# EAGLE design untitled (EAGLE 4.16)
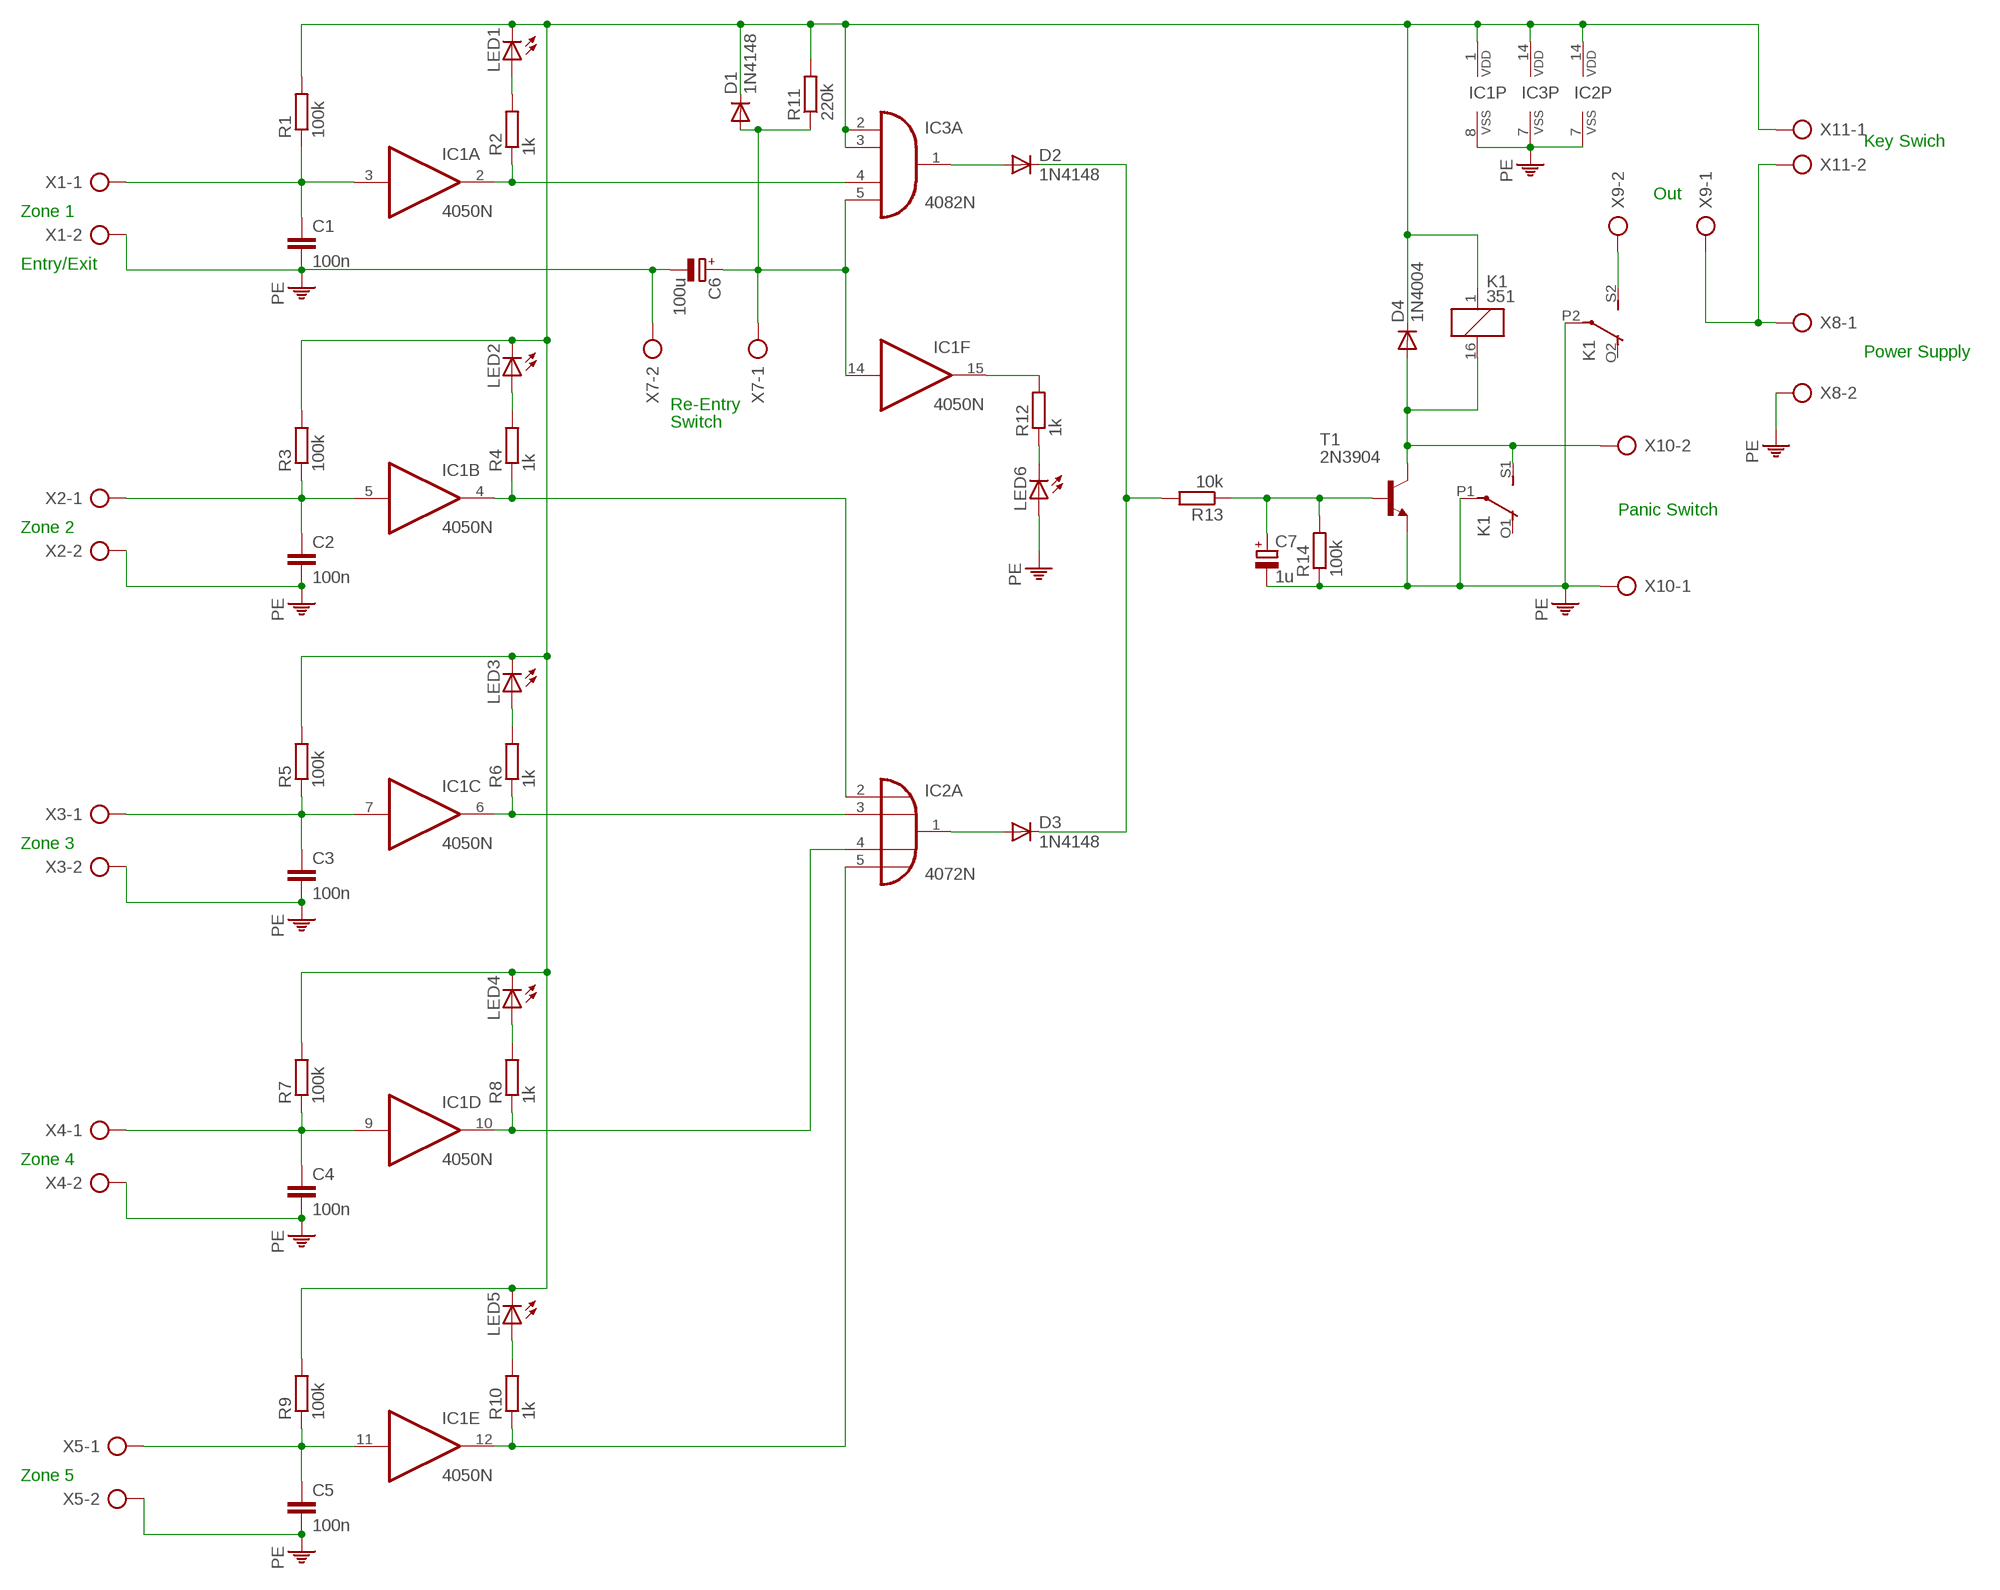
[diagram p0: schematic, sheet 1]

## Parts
C1  100n  C-EU050-024X044  [C050-024X044]
C2  100n  C-EU050-024X044  [C050-024X044]
C3  100n  C-EU050-024X044  [C050-024X044]
C4  100n  C-EU050-024X044  [C050-024X044]
C5  100n  C-EU050-024X044  [C050-024X044]
C6  100u  CPOL-EUE5-8.5  [E5-8,5]
C7  1u  CPOL-EUE5-6  [E5-6]
D1  1N4148  [DO35-10]
D2  1N4148  [DO35-10]
D3  1N4148  [DO35-10]
D4  1N4004  [DO41-10]
IC1  4050N  [DIL16]
IC2  4072N  [DIL14]
IC3  4082N  [DIL14]
K1  351  [351]
LED1  LED5MM  [LED5MM]
LED2  LED5MM  [LED5MM]
LED3  LED5MM  [LED5MM]
LED4  LED5MM  [LED5MM]
LED5  LED5MM  [LED5MM]
LED6  LED5MM  [LED5MM]
R1  100k  R-EU_0207/10  [0207/10]
R2  1k  R-EU_0207/10  [0207/10]
R3  100k  R-EU_0207/10  [0207/10]
R4  1k  R-EU_0207/10  [0207/10]
R5  100k  R-EU_0207/10  [0207/10]
R6  1k  R-EU_0207/10  [0207/10]
R7  100k  R-EU_0207/10  [0207/10]
R8  1k  R-EU_0207/10  [0207/10]
R9  100k  R-EU_0207/10  [0207/10]
R10  1k  R-EU_0207/10  [0207/10]
R11  220k  R-EU_0207/10  [0207/10]
R12  1k  R-EU_0207/10  [0207/10]
R13  10k  R-EU_0207/10  [0207/10]
R14  100k  R-EU_0207/10  [0207/10]
T1  2N3904  [TO92]
X1  AK300/2  [AK300/2]
X2  AK300/2  [AK300/2]
X3  AK300/2  [AK300/2]
X4  AK300/2  [AK300/2]
X5  AK300/2  [AK300/2]
X7  AK300/2  [AK300/2]
X8  AK300/2  [AK300/2]
X9  AK300/2  [AK300/2]
X10  AK300/2  [AK300/2]
X11  AK300/2  [AK300/2]

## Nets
+12V: D1.C D4.C IC1.1(P:VDD) IC2.14(P:VDD) IC3.2(A:I0) IC3.3(A:I1) IC3.14(P:VDD) K1.1 LED1.K(C) LED2.K(C) LED3.K(C) LED4.K(C) LED5.K(C) R1.2 R3.2 R5.2 R7.2 R9.2 R11.2 X11.1
N$1: C1.1 IC1.3(A:I) R1.1 X1.1
N$2: IC1.2(A:O) IC3.4(A:I2) R2.1
N$3: LED1.A R2.2
N$4: C6.+ D1.A IC1.14(F:I) IC3.5(A:I3) R11.1 X7.1
N$5: LED2.A R4.2
N$6: C2.1 IC1.5(B:I) R3.1 X2.1
N$7: LED3.A R6.2
N$8: IC1.4(B:O) IC2.2(A:I0) R4.1
N$9: LED4.A R8.2
N$10: IC1.15(F:O) R12.2
N$11: LED6.K(C) R12.1
N$12: LED5.A R10.2
N$13: IC1.6(C:O) IC2.3(A:I1) R6.1
N$14: C3.1 IC1.7(C:I) R5.1 X3.1
N$15: D3.A IC2.1(A:O)
N$16: D2.A IC3.1(A:O)
N$17: C4.1 IC1.9(D:I) R7.1 X4.1
N$18: IC1.10(D:O) IC2.4(A:I2) R8.1
N$20: D2.C D3.C R13.2
N$21: C5.1 IC1.11(E:I) R9.1 X5.1
N$22: IC1.12(E:O) IC2.5(A:I3) R10.1
N$24: C7.+ R13.1 R14.2 T1.2(B)
N$26: D4.A K1.16 K1.S1(2:S) T1.1(C) X10.2
N$27: K1.S2(3:S) X9.2
N$28: X8.1 X9.1 X11.2
PE: C1.2 C2.2 C3.2 C4.2 C5.2 C6.- C7.- IC1.8(P:VSS) IC2.7(P:VSS) IC3.7(P:VSS) K1.P1(2:P) K1.P2(3:P) LED6.A R14.1 T1.3(E) X1.2 X2.2 X3.2 X4.2 X5.2 X7.2 X8.2 X10.1
Unconnected: IC2.9(B:I0) IC2.10(B:I1) IC2.11(B:I2) IC2.12(B:I3) IC2.13(B:O) IC3.9(B:I0) IC3.10(B:I1) IC3.11(B:I2) IC3.12(B:I3) IC3.13(B:O) K1.O1(2:O) K1.O2(3:O)

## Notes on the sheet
- Key Swich
- Out
- Zone 1
- Entry/Exit
- Power Supply
- Re-Entry
- Switch
- Panic Switch
- Zone 2
- Zone 3
- Zone 4
- Zone 5

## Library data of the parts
C1-C5 = rcl:C-EU: CAPACITOR, European symbol
C6 C7 = rcl:CPOL-EU: POLARIZED CAPACITOR, European symbol
D1-D3 = diode:1N4148: DIODE
D4 = diode:1N4004: DIODE
IC1 = 40xx:4050: Hex non-inverting BUFFER
IC2 = 40xx:4072: Dual 4-input OR
IC3 = 40xx:4082: Dual 4-input AND
K1 = relay:351: RELAY 2 x switch, Omron
LED1-LED6 = led:LED: LED
R1-R14 = rcl:R-EU_: RESISTOR, European symbol
T1 = transistor:2N3904: NPN TRANSISTOR
X1-X5 X7-X11 = con-ptr500:AK300/2: CONNECTOR

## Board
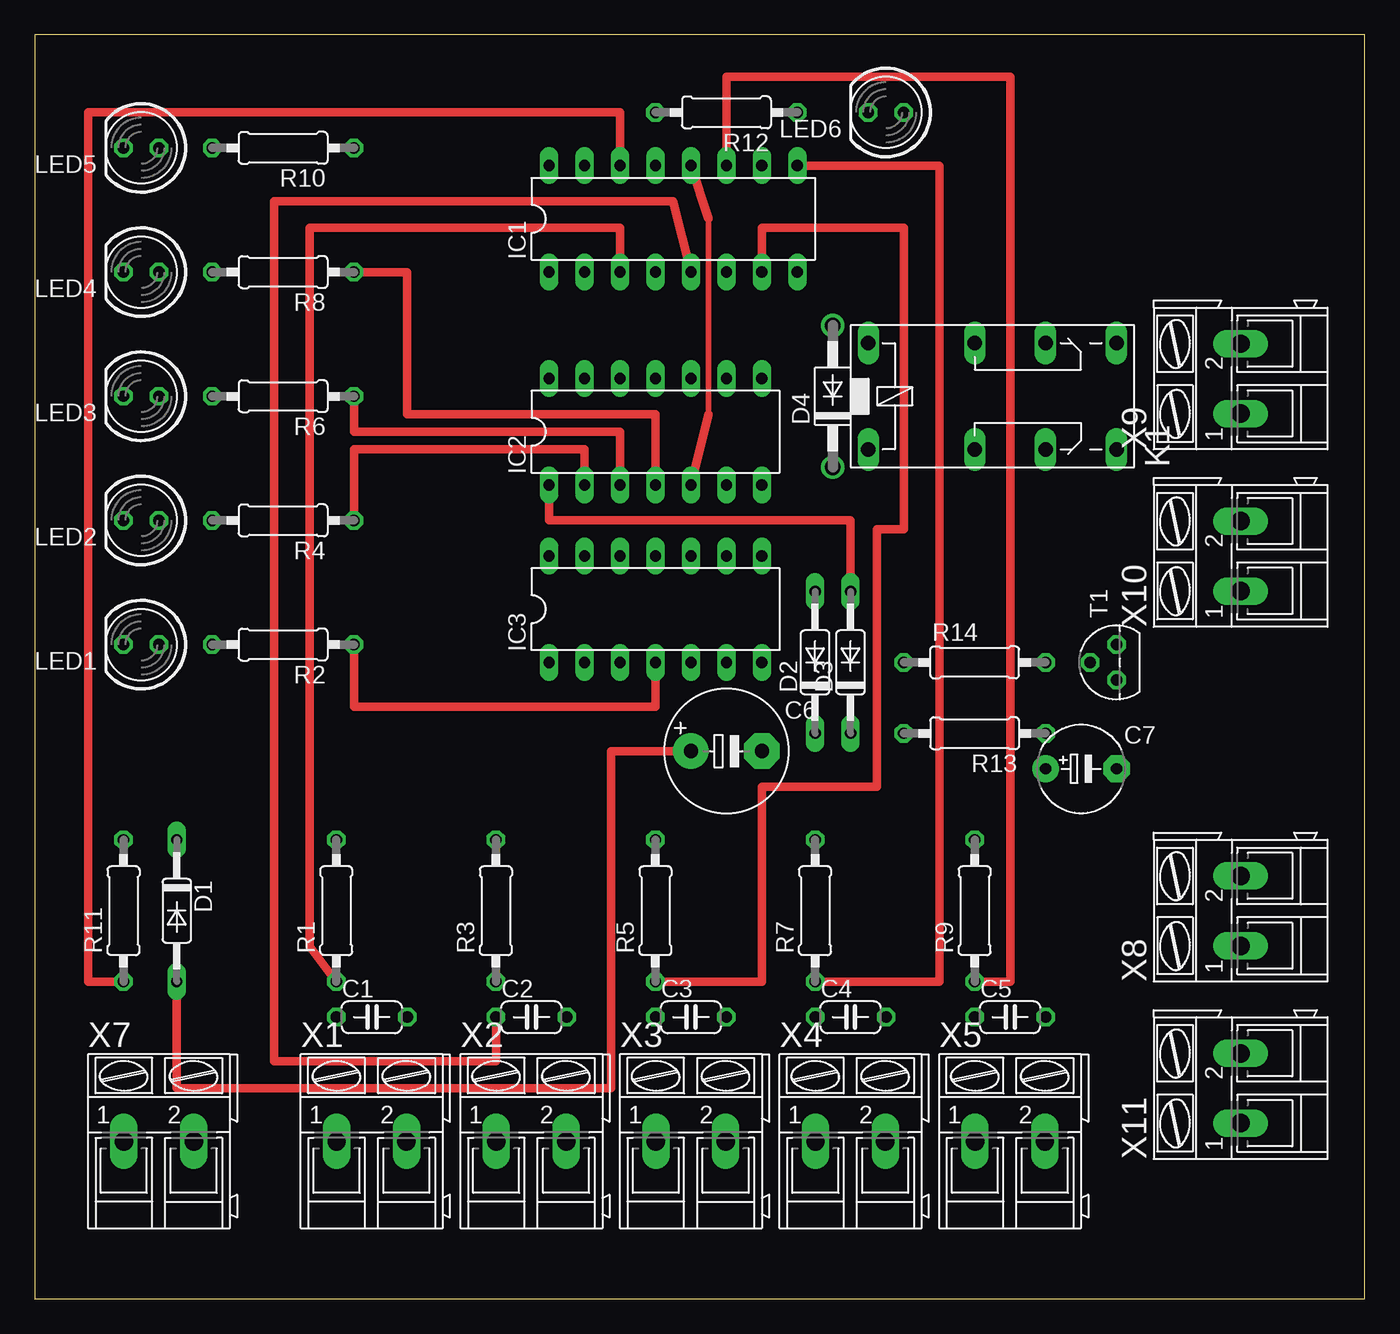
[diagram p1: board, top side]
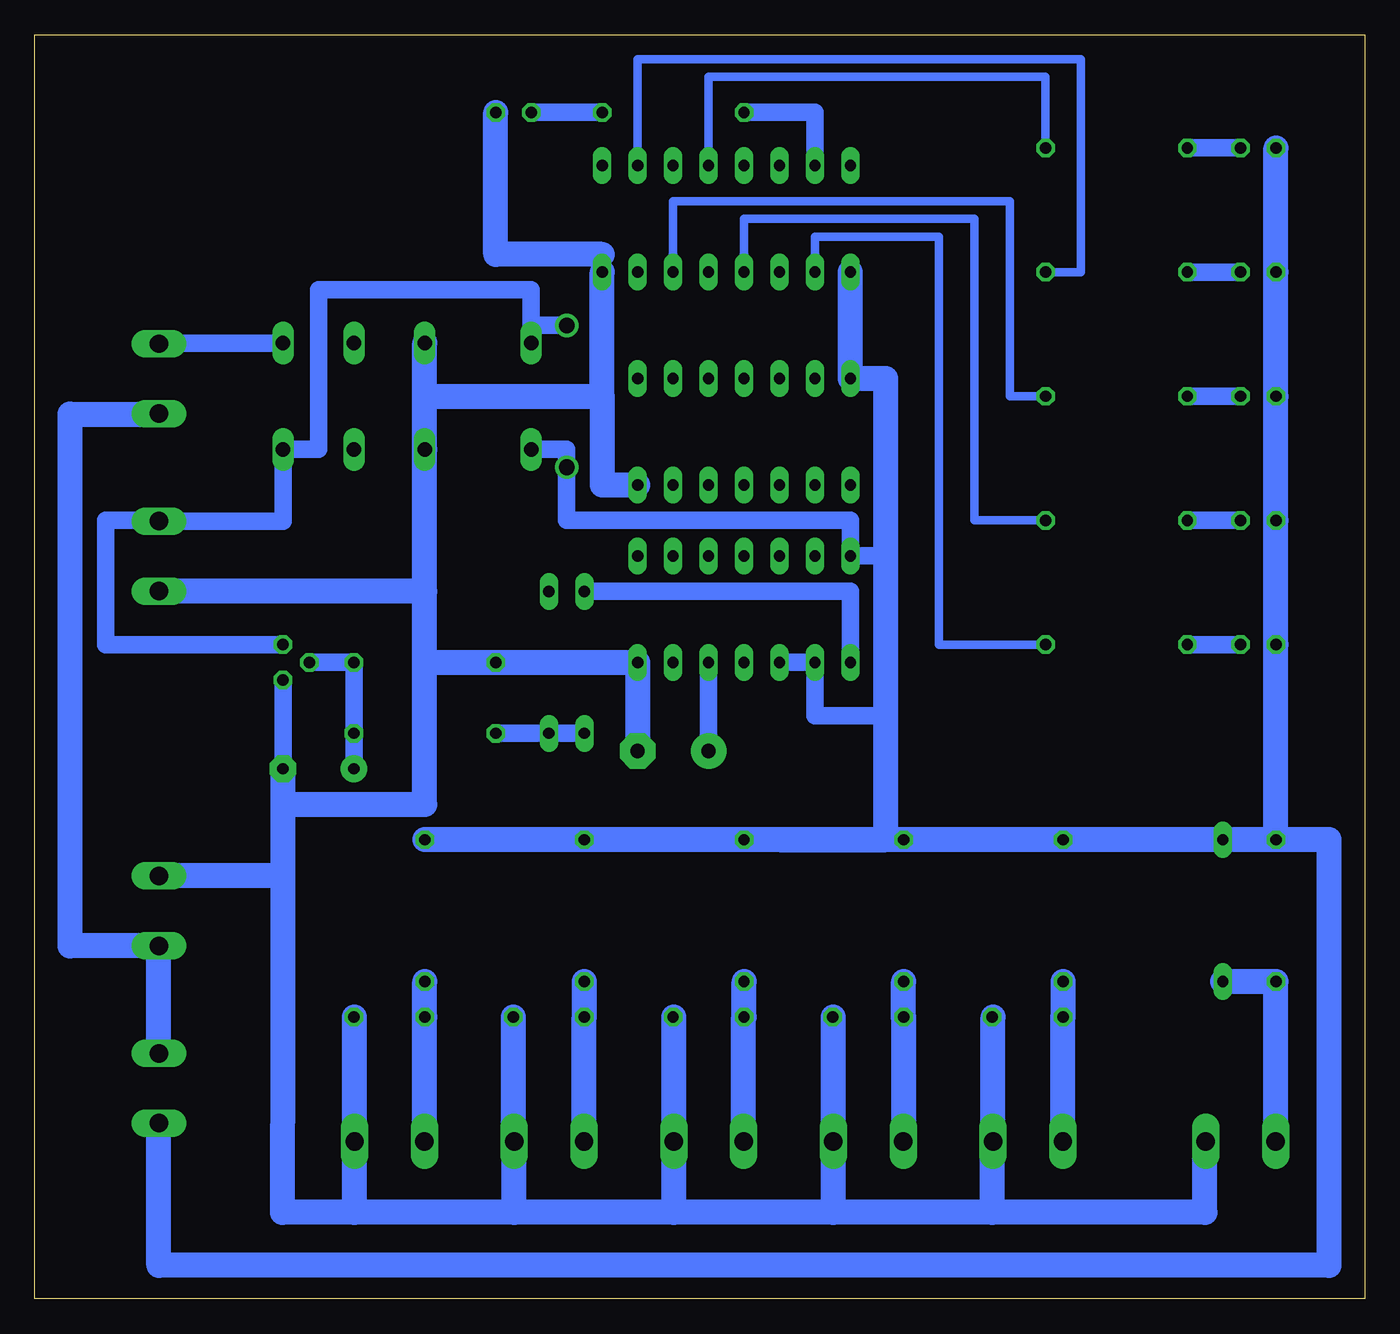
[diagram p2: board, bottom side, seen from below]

Size 95.23 x 90.48 mm. Coordinates in mm from the lower left corner, seen from the top.
Outline: 0,0 95.23,0 95.23,90.48 0,90.48 0,0
Copper layers (1*16): Fls 0.035mm / dielectric 1.5mm / Alsó   0.035mm
Design rules "default": minimum track width 10mil, minimum drill 24mil, track to track 8mil, track to pad 8mil, pad to pad 8mil, via to via 8mil, smd to smd 8mil, copper to edge 40mil, drill to drill 8mil, minimum pad ring 10mil, minimum via ring 8mil, stop-mask expansion 4mil, vias tented up to drill 0mil, thermal gap 10mil

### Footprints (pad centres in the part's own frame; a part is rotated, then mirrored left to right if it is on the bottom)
C050-024X044 = drill 0.813 octagon: 1 -2.54,0; 2 2.54,0
E5-8,5 = drill 1.016 pad 2.54 round: + -2.54,0 | drill 1.016 pad 2.54 octagon: - 2.54,0
E5-6 = drill 0.813 pad 1.905 round: + -2.54,0 | drill 0.813 pad 1.905 octagon: - 2.54,0
DO35-10 = drill 0.813 long: A 5.08,0; C -5.08,0
DO41-10 = drill 1.118 round: A 5.08,0; C -5.08,0
DIL16 = drill 0.813 long: 1 -8.89,-3.81; 2 -6.35,-3.81; 3 -3.81,-3.81; 4 -1.27,-3.81; 5 1.27,-3.81; 6 3.81,-3.81; 7 6.35,-3.81; 8 8.89,-3.81; 9 8.89,3.81; 10 6.35,3.81; 11 3.81,3.81; 12 1.27,3.81; 13 -1.27,3.81; 14 -3.81,3.81; 15 -6.35,3.81; 16 -8.89,3.81
DIL14 = drill 0.813 long: 1 -7.62,-3.81; 2 -5.08,-3.81; 3 -2.54,-3.81; 4 0,-3.81; 5 2.54,-3.81; 6 5.08,-3.81; 7 7.62,-3.81; 8 7.62,3.81; 9 5.08,3.81; 10 2.54,3.81; 11 0,3.81; 12 -2.54,3.81; 13 -5.08,3.81; 14 -7.62,3.81
351 = drill 1.016 long: 1 -3.81,-3.81; 16 -3.81,3.81; O1 8.89,-3.81; O2 8.89,3.81; P1 3.81,-3.81; P2 3.81,3.81; S1 13.97,-3.81; S2 13.97,3.81
LED5MM = drill 0.813 octagon: A -1.27,0; K 1.27,0
0207/10 = drill 0.813 octagon: 1 -5.08,0; 2 5.08,0
TO92 = drill 0.813 octagon: 1 1.27,0; 2 0,1.905; 3 -1.27,0
AK300/2 = drill 1.321 long: 1 -2.515,0; 2 2.489,0

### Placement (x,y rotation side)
C1  24.12,20.16 0 top
C2  35.55,20.16 0 top
C3  46.98,20.16 0 top
C4  58.41,20.16 0 top
C5  69.84,20.16 0 top
C6  49.52,39.2 0 top
C7  74.93,37.94 0 top
D1  10.15,27.77 270 top
D2  55.88,45.55 90 top
D3  58.41,45.55 90 top
D4  57.14,64.61 90 top
IC1  45.71,77.31 0 top
IC2  44.45,62.06 0 top
IC3  44.45,49.37 0 top
K1  63.49,64.61 0 top
LED1  7.62,46.82 180 top
LED2  7.62,55.71 180 top
LED3  7.62,64.61 180 top
LED4  7.62,73.5 180 top
LED5  7.62,82.39 180 top
LED6  60.95,84.93 180 top
R1  21.59,27.77 90 top
R2  17.78,46.82 180 top
R3  33.02,27.77 90 top
R4  17.78,55.71 180 top
R5  44.45,27.77 90 top
R6  17.78,64.61 180 top
R7  55.88,27.77 90 top
R8  17.78,73.5 180 top
R9  67.31,27.77 90 top
R10  17.78,82.39 180 top
R11  6.34,27.77 90 top
R12  49.52,84.93 180 top
R13  67.31,40.48 180 top
R14  67.31,45.55 0 top
T1  77.47,45.55 90 top
X1  24.12,11.27 0 top
X2  35.55,11.27 0 top
X3  46.98,11.27 0 top
X4  58.41,11.27 0 top
X5  69.84,11.27 0 top
X7  8.88,11.27 0 top
X8  86.36,27.77 90 top
X9  86.36,65.88 90 top
X10  86.36,53.17 90 top
X11  86.36,15.07 90 top

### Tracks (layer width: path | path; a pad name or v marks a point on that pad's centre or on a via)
+12V
  Alsó   1.27: K1.1 57.14,60.8 D4.C 57.14,55.71 36.82,55.71 IC3.14 34.28,53.17 | IC3.3 IC3.2 39.36,41.74 34.28,41.74
  Alsó   1.778: LED5.K LED4.K LED3.K LED2.K LED1.K R11.2 | R11.2 D1.C R1.2 R3.2 41.9,32.86 | 41.9,32.86 R5.2 R7.2 R9.2 | X11.1 86.36,2.38 2.54,2.38 2.54,32.86 R11.2 | 41.9,32.86 34.28,32.86 34.28,41.74 34.28,53.17 34.28,65.88 IC2.14 IC1.1
N$1
  Fls 0.61: IC1.3 41.9,76.67 19.68,76.67 19.68,25.23 R1.1
  Alsó   1.27: 21.61,20.16 C1.1
  Alsó   1.778: X1.1 21.61,20.16 | C1.1 R1.1
N$2
  Fls 0.61: IC3.4 44.45,42.38 22.86,42.38 R2.1
  Alsó   0.61: IC1.2 39.36,76.04 30.48,76.04 30.48,46.82 R2.1
N$3
  Alsó   1.27: LED1.A R2.2
N$4
  Fls 0.61: C6.+ 41.27,39.2 41.27,15.07 10.15,15.07 D1.A | IC1.14 41.9,84.93 3.81,84.93 3.81,22.7 R11.1
  Alsó   1.27: 6.37,22.7 R11.1 | C6.+ IC3.5
  Alsó   1.778: X7.1 6.37,22.7 | R11.1 D1.A
N$5
  Alsó   1.27: LED2.A R4.2
N$6
  Fls 0.61: IC1.5 45.71,78.58 17.14,78.58 17.14,16.98 33.02,16.98 C2.1
  Alsó   1.27: C2.1 33.04,20.16
  Alsó   1.778: 33.04,20.16 X2.1 | C2.1 R3.1
N$7
  Alsó   1.27: LED3.A R6.2
N$8
  Fls 0.61: IC2.2 39.36,60.8 22.86,60.8 R4.1
  Alsó   0.61: IC1.4 44.45,77.31 27.94,77.31 27.94,55.71 R4.1
N$9
  Alsó   1.27: LED4.A R8.2
N$10
  Alsó   1.27: R12.2 39.36,84.93 IC1.15
N$11
  Alsó   1.27: R12.1 LED6.K
N$12
  Alsó   1.27: LED5.A R10.2
N$13
  Fls 0.61: IC2.3 41.9,62.06 22.86,62.06 R6.1
  Alsó   0.61: R6.1 25.39,64.61 25.39,78.58 49.52,78.58 IC1.6
N$14
  Fls 0.61: R5.1 52.06,22.7 52.06,36.66 60.32,36.66 60.32,55.08 62.22,55.08 62.22,76.67 52.06,76.67 IC1.7
  Alsó   1.27: 44.47,20.16 C3.1
  Alsó   1.778: X3.1 44.47,20.16 | C3.1 R5.1
N$15
  Fls 0.61: D3.A 58.41,55.71 36.82,55.71 IC2.1
N$16
  Alsó   1.27: IC3.1 36.82,50.63 D2.A
N$17
  Fls 0.61: R7.1 64.77,22.7 64.77,81.12 IC1.9
  Alsó   1.27: 55.9,20.16 C4.1
  Alsó   1.778: X4.1 55.9,20.16 | C4.1 R7.1
N$18
  Fls 0.61: IC2.4 44.45,63.34 26.67,63.34 26.67,73.5 R8.1
  Alsó   0.61: IC1.10 52.06,88.73 20.32,88.73 20.32,73.5 R8.1
N$20
  Alsó   1.27: D2.C D3.C R13.2
N$21
  Fls 0.61: R9.1 69.84,22.7 69.84,87.47 49.52,87.47 IC1.11
  Alsó   1.27: 67.33,20.16 C5.1
  Alsó   1.778: X5.1 67.33,20.16 | C5.1 R9.1
N$22
  Fls 0.406: 48.25,63.34 48.25,77.31
  Fls 0.61: IC2.5 48.25,63.34 | 48.25,77.31 IC1.12
  Alsó   0.61: R10.1 22.86,87.47 46.98,87.47 IC1.12
N$24
  Alsó   1.27: R13.1 R14.2 | R14.2 T1.2 | R13.1 R14.2 | R13.1 R14.2 | C7.+ R13.1
N$26
  Alsó   1.27: 59.68,69.69 59.68,72.23 74.93,72.23 74.93,60.8 K1.S1 77.47,55.66 X10.2 86.36,55.71 90.17,55.71 90.17,46.82 T1.1 | 59.68,69.69 K1.16 | 59.68,69.69 D4.A
N$27
  Alsó   1.27: X9.2 86.36,68.42 K1.S2
N$28
  Alsó   1.27: 86.36,63.34 X9.1
  Alsó   1.778: 86.36,63.34 92.7,63.34 92.7,25.26 X8.1 X11.2
PE
  Alsó   1.27: X4.2 60.95,11.27 | 49.47,20.16 C3.2 | 38.04,20.16 C2.2 | 26.61,20.16 C1.2 | 72.33,20.16 C5.2 | 86.36,50.63 X10.1 | C7.- T1.3 | 77.47,30.31 77.47,30.26 | IC1.8 54.6,74.77
  Alsó   1.778: X7.2 11.42,11.27 11.42,6.19 26.67,6.19 | 26.67,6.19 26.67,11.27 X1.2 26.61,20.16 | 38.04,6.19 X2.2 38.04,20.16 | 26.67,6.19 38.04,6.19 | 49.47,6.19 X3.2 49.47,20.16 | 38.04,6.19 49.47,6.19 | 60.9,6.19 X4.2 | 49.47,6.19 60.9,6.19 | 72.33,6.19 X5.2 72.33,20.16 | 60.9,6.19 72.33,6.19 | 72.33,6.19 77.49,6.19 77.47,18.89 77.47,30.31 77.47,35.4 | 60.95,11.27 C4.2 | 67.31,64.61 K1.P1 67.31,50.63 | 67.31,64.61 K1.P2 | 67.31,50.63 86.36,50.63 | 77.47,35.4 C7.- | 54.6,64.61 IC1.8 | 67.31,64.61 54.6,64.61 | IC2.7 54.6,58.26 54.6,64.61 | 67.31,45.55 67.31,35.4 77.47,35.4 | 67.31,45.55 67.31,50.63 | 77.47,30.26 X8.2 | LED6.A 62.22,74.77 54.6,74.77 | 67.31,45.55 R14.1 IC3.7 C6.-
